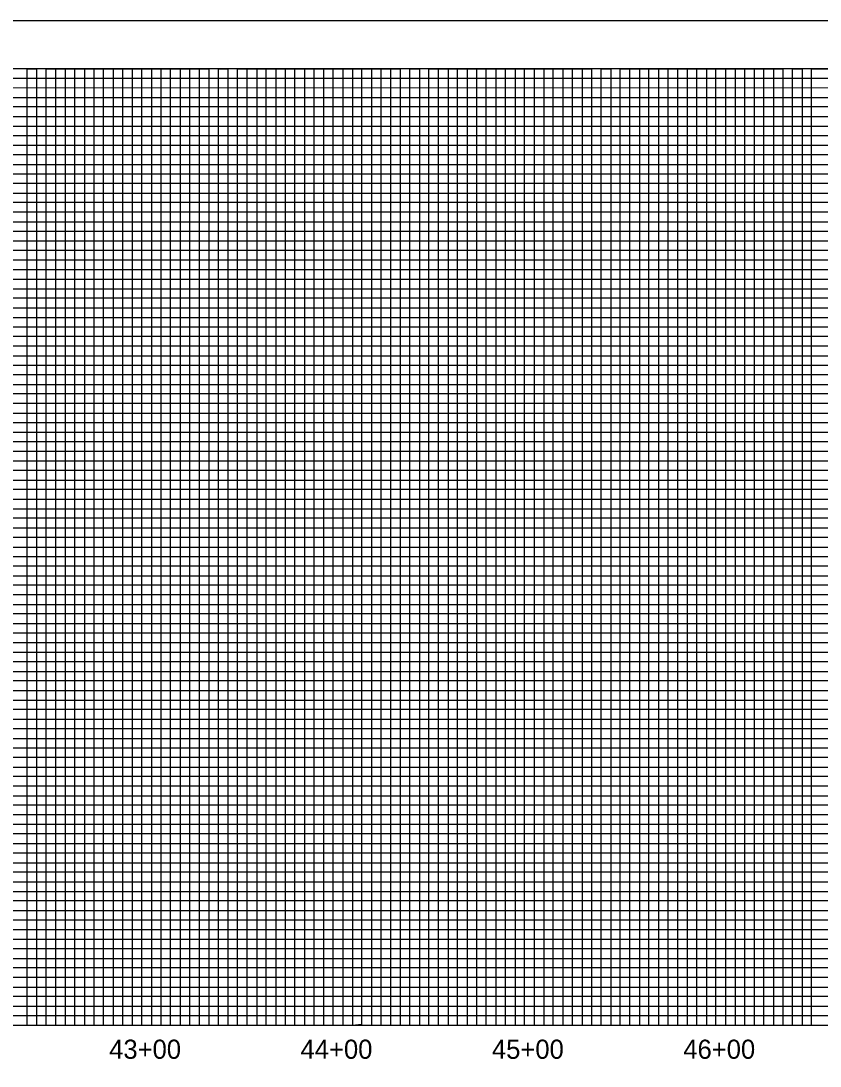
# Model space of a CAD drawing. Extents: x 505602 to 507286, y 483109 to 484209.
# Drawn here: x 506451 to 506868, y 483662 to 484209 of the extents above; entities that cross this region are included whole.
import ezdxf

# ---------------------------------------------------------------- set-up
doc = ezdxf.new("R2010")
doc.units = 0
for name, color, linetype in [('Exist Vertical Profile Vertical Axis Label', 7, 'Continuous'), ('Sheet Layout Profile Border Port 1', 7, 'Continuous'), ('Sheet Plot Border Outside CELL', 7, 'Continuous'), ('Sheet Profile CELL', 7, 'Continuous'), ('Sheet Profile Grid Major CELL', 7, 'Continuous'), ('Sheet Profile Grid Middle CELL', 7, 'Continuous'), ('Sheet Profile Grid Minor CELL', 7, 'Continuous')]:
    doc.layers.add(name, color=color, linetype=linetype)

msp = doc.modelspace()

# ---------------------------------------------------------------- linework, layer by layer
at = {"layer": 'Sheet Layout Profile Border Port 1'}
msp.add_lwpolyline([(505819.08, 484183.71), (505819.08, 483683.71), (507219.08, 483683.71), (507219.08, 484022.66), (507069.03, 484022.66), (507069.03, 484183.71)], close=True, dxfattribs=at)
at = {"layer": 'Sheet Plot Border Outside CELL'}
msp.add_lwpolyline([(505602.08, 483108.71), (507286.08, 483108.71), (507286.08, 484208.71), (505602.08, 484208.71)], close=True, dxfattribs=at)
at = {"layer": 'Sheet Profile CELL'}
msp.add_line((505769.08, 483683.71), (507269.08, 483683.71), dxfattribs=at)
msp.add_lwpolyline([(507269.08, 484183.71), (505769.08, 484183.71), (505769.08, 483133.71), (507269.08, 483133.71)], close=True, dxfattribs=at)
at = {"layer": 'Sheet Profile Grid Major CELL'}
for points in [[(506419.08, 483683.71), (506469.08, 483683.71), (506469.08, 484183.71), (506519.08, 484183.71), (506519.08, 483683.71), (506569.08, 483683.71), (506569.08, 484183.71), (506619.08, 484183.71), (506619.08, 483683.71), (506669.08, 483683.71), (506669.08, 484183.71), (506719.08, 484183.71), (506719.08, 483683.71), (506769.08, 483683.71), (506769.08, 484183.71), (506819.08, 484183.71), (506819.08, 483683.71), (506869.08, 483683.71)], [(505769.08, 484133.71), (507069.08, 484133.71)], [(507069.08, 484083.71), (505769.08, 484083.71), (505769.08, 484033.71), (507069.08, 484033.71)], [(507269.08, 483983.71), (505769.08, 483983.71), (505769.08, 483933.71), (507269.08, 483933.71)], [(507269.08, 483883.71), (505769.08, 483883.71), (505769.08, 483833.71), (507269.08, 483833.71)], [(507269.08, 483783.71), (505769.08, 483783.71), (505769.08, 483783.71), (505769.08, 483733.71), (507269.08, 483733.71)]]:
    msp.add_lwpolyline(points, dxfattribs=at)
at = {"layer": 'Sheet Profile Grid Middle CELL'}
msp.add_line((505769.08, 484158.71), (507069.03, 484158.71), dxfattribs=at)
for points in [[(506444.08, 483683.71), (506494.08, 483683.71), (506494.08, 484183.71), (506544.08, 484183.71), (506544.08, 483683.71), (506594.08, 483683.71), (506594.08, 484183.71), (506644.08, 484183.71), (506644.08, 483683.71), (506694.08, 483683.71), (506694.08, 484183.71), (506744.08, 484183.71), (506744.08, 483683.71), (506794.08, 483683.71), (506794.08, 484183.71), (506844.08, 484183.71), (506844.08, 483683.71), (506894.08, 483683.71)], [(507069.08, 484108.71), (505769.08, 484108.71), (505769.08, 484058.71), (507069.08, 484058.71)], [(507269.08, 484008.71), (505769.08, 484008.71), (505769.08, 483958.71), (507094.08, 483958.71)], [(507269.08, 483908.71), (505769.08, 483908.71), (505769.08, 483858.71), (507269.08, 483858.71)], [(507269.08, 483808.71), (505769.08, 483808.71), (505769.08, 483758.71), (507269.08, 483758.71)], [(507269.08, 483708.71), (505769.08, 483708.71)]]:
    msp.add_lwpolyline(points, dxfattribs=at)
at = {"layer": 'Sheet Profile Grid Minor CELL'}
for p, q in [((505819.08, 484178.71), (507069.08, 484178.71)), ((507069.08, 484173.71), (505819.08, 484173.36)), ((505819.08, 484168.71), (507069.08, 484168.71)), ((507069.03, 484048.71), (505819.08, 484048.71)), ((507069.08, 484043.71), (505819.08, 484043.71)), ((507069.08, 484038.71), (505819.08, 484038.71)), ((505819.08, 484028.71), (507069.08, 484028.71)), ((507069.08, 484023.71), (505819.08, 484023.71)), ((505819.08, 484018.71), (507219.08, 484018.71)), ((507219.08, 483998.71), (505819.08, 483998.71)), ((505819.08, 483993.71), (507219.08, 483993.71)), ((507219.08, 483973.71), (505819.08, 483973.71)), ((505819.08, 483968.71), (507219.08, 483968.71)), ((507219.08, 483948.71), (505819.08, 483948.71)), ((505819.08, 483943.71), (507219.08, 483943.71)), ((507219.08, 483938.71), (505819.08, 483938.71)), ((505819.08, 483928.71), (507219.08, 483928.71)), ((507219.08, 483923.71), (505819.08, 483923.71)), ((505819.08, 483918.71), (507219.08, 483918.71)), ((507219.08, 483913.71), (505819.08, 483913.71)), ((505819.08, 483903.71), (507219.08, 483903.71)), ((507219.08, 483898.71), (505819.08, 483898.71)), ((505819.08, 483893.71), (507219.08, 483893.71)), ((507219.08, 483888.71), (505819.08, 483888.71)), ((505819.08, 483878.71), (507219.08, 483878.71)), ((507219.08, 483873.71), (505819.08, 483873.71)), ((505819.08, 483868.71), (507219.08, 483868.71)), ((507219.08, 483863.71), (505819.08, 483863.71)), ((505819.08, 483853.71), (507219.08, 483853.71)), ((507219.08, 483848.71), (505819.08, 483848.71)), ((505819.08, 483843.71), (507219.08, 483843.71)), ((507219.08, 483838.71), (505819.08, 483838.71)), ((505819.08, 483828.71), (507219.08, 483828.71)), ((507219.08, 483823.71), (505819.08, 483823.71)), ((505819.08, 483818.71), (507219.08, 483818.71)), ((507219.08, 483813.71), (505819.08, 483813.71)), ((505819.08, 483803.71), (507219.08, 483803.71)), ((507219.08, 483798.71), (505819.08, 483798.71)), ((507219.08, 483793.71), (505819.08, 483793.71)), ((507219.08, 483788.71), (505819.08, 483788.71)), ((505819.08, 483778.71), (507219.08, 483778.71)), ((507219.08, 483773.71), (505819.08, 483773.71)), ((505819.08, 483768.71), (507219.08, 483768.71)), ((507219.08, 483763.71), (505819.08, 483763.71)), ((505819.08, 483753.71), (507219.08, 483753.71)), ((507219.08, 483748.71), (505819.08, 483748.71)), ((505819.08, 483743.71), (507219.08, 483743.71)), ((507219.08, 483738.71), (505819.08, 483738.71)), ((505819.08, 483728.71), (507219.08, 483728.71)), ((507219.08, 483723.71), (505819.08, 483723.71)), ((505819.08, 483718.71), (507219.08, 483718.71)), ((507219.08, 483713.71), (505819.08, 483713.71)), ((505819.08, 483703.71), (507219.08, 483703.71)), ((507219.08, 483698.71), (505819.08, 483698.71)), ((505819.08, 483693.71), (507219.08, 483693.71))]:
    msp.add_line(p, q, dxfattribs=at)
for points in [[(506449.08, 483683.71), (506454.08, 483683.71), (506454.08, 484183.71), (506459.08, 484183.71), (506459.08, 483683.71), (506464.08, 483683.71), (506464.08, 484183.71), (506474.08, 484183.71), (506474.08, 483683.71), (506474.08, 483683.71), (506479.08, 483683.71), (506479.08, 484183.71), (506484.08, 484183.71), (506484.08, 483683.71), (506489.08, 483683.71), (506489.08, 484183.71), (506499.08, 484183.71), (506499.08, 483683.71), (506504.08, 483683.71), (506504.08, 484183.71), (506509.08, 484183.71), (506509.08, 483683.71), (506514.08, 483683.71), (506514.08, 484183.71), (506524.08, 484183.71), (506524.08, 483683.71), (506529.08, 483683.71), (506529.08, 484183.71), (506534.08, 484183.71), (506534.08, 483683.71), (506539.08, 483683.71), (506539.08, 484183.71), (506549.08, 484183.71), (506549.08, 483683.71), (506554.08, 483683.71), (506554.08, 484183.71), (506559.08, 484183.71), (506559.08, 483683.71), (506564.08, 483683.71), (506564.08, 484183.71), (506574.08, 484183.71), (506574.08, 483683.71), (506579.08, 483683.71), (506579.08, 484183.71), (506584.08, 484183.71), (506584.08, 483683.71), (506589.08, 483683.71), (506589.08, 484183.71), (506599.08, 484183.71), (506599.08, 483683.71), (506604.08, 483683.71), (506604.08, 484183.71), (506609.08, 484183.71), (506609.08, 483683.71), (506614.08, 483683.71), (506614.08, 484183.71), (506624.08, 484183.71), (506624.08, 483683.71), (506628.78, 483684.26), (506629.08, 483683.71), (506629.08, 484183.71), (506634.08, 484183.71), (506634.08, 483683.71), (506639.08, 483683.71), (506639.08, 484183.71), (506649.08, 484183.71), (506649.08, 483683.71), (506654.08, 483683.71)], [(506654.08, 483683.71), (506654.08, 484183.71), (506659.08, 484183.71), (506659.08, 483683.71), (506664.08, 483683.71), (506664.08, 484183.71), (506674.08, 484183.71), (506674.08, 483683.71), (506679.08, 483683.71), (506679.08, 484183.71), (506684.08, 484183.71), (506684.08, 483683.71), (506689.08, 483683.71), (506689.08, 484183.71), (506699.08, 484183.71), (506699.08, 483683.71), (506704.08, 483683.71), (506704.08, 484183.71), (506709.08, 484183.71), (506709.08, 483683.71), (506714.08, 483683.71), (506714.08, 484183.71), (506724.08, 484183.71), (506724.08, 483683.71), (506729.08, 483683.71), (506729.08, 484183.71), (506734.08, 484183.71), (506734.08, 483683.71), (506739.08, 483683.71), (506739.08, 484183.71), (506749.08, 484183.71), (506749.08, 483683.71), (506754.08, 483683.71), (506754.08, 484183.71), (506759.08, 484183.71), (506759.08, 483683.71), (506764.08, 483683.71), (506764.08, 484183.71), (506774.08, 484183.71), (506774.08, 483683.71), (506779.08, 483683.71), (506779.08, 484183.71), (506784.08, 484183.71), (506784.08, 483683.71), (506789.08, 483683.71), (506789.08, 484183.71), (506799.08, 484183.71), (506799.08, 483683.71), (506804.08, 483683.71), (506804.08, 484183.71), (506809.08, 484183.71), (506809.08, 483683.71), (506814.08, 483683.71), (506814.08, 484183.71), (506824.08, 484183.71), (506824.08, 483683.71), (506829.08, 483683.71), (506829.08, 484183.71), (506834.08, 484183.71), (506834.08, 483683.71), (506839.08, 483683.71), (506839.08, 484183.71), (506849.08, 484183.71), (506849.08, 483683.71), (506854.08, 483683.71), (506854.08, 484183.71), (506859.08, 484183.71), (506859.08, 483683.71), (506864.08, 483683.71), (506864.08, 484183.71), (506874.08, 484183.71)], [(507069.08, 484163.71), (505819.08, 484163.71), (505819.08, 484153.71), (507069.08, 484153.71)], [(507069.03, 484148.71), (505819.08, 484148.71), (505819.08, 484143.71), (507069.08, 484143.71)], [(507069.08, 484138.71), (505819.08, 484138.71), (505819.08, 484128.71), (507069.08, 484128.71)], [(507069.08, 484123.71), (505819.08, 484123.71), (505819.08, 484118.71), (507069.08, 484118.71)], [(507069.08, 484113.71), (505819.08, 484113.71), (505819.08, 484103.71), (507069.08, 484103.71)], [(507069.08, 484098.71), (505819.08, 484098.71), (505819.08, 484093.71), (507069.08, 484093.71)], [(507069.08, 484088.71), (505819.08, 484088.71), (505819.08, 484078.71), (507069.08, 484078.71)], [(507069.08, 484073.61), (505819.18, 484073.61), (505819.18, 484068.71), (507069.08, 484068.71)], [(507069.08, 484063.71), (505819.08, 484063.71), (505819.08, 484053.71), (507069.08, 484053.71)], [(507219.08, 484013.71), (505819.08, 484013.71), (505819.08, 484003.71), (507219.08, 484003.71)], [(507219.08, 483988.71), (505819.08, 483988.71), (505819.08, 483978.71), (507219.08, 483978.71)], [(507219.08, 483963.71), (505819.08, 483963.71), (505819.08, 483953.71), (507219.08, 483953.71)], [(507219.08, 483688.71), (505819.08, 483688.71)]]:
    msp.add_lwpolyline(points, dxfattribs=at)

# ---------------------------------------------------------------- texts
at = {"layer": 'Exist Vertical Profile Vertical Axis Label'}
for s, p in [('43+00', (506497.01, 483666.21)), ('44+00', (506597.01, 483666.21)), ('45+00', (506697.01, 483666.21)), ('46+00', (506797.01, 483666.21))]:
    msp.add_text(s, height=10, dxfattribs=at).set_placement(p)

doc.saveas('drawing.dxf')
